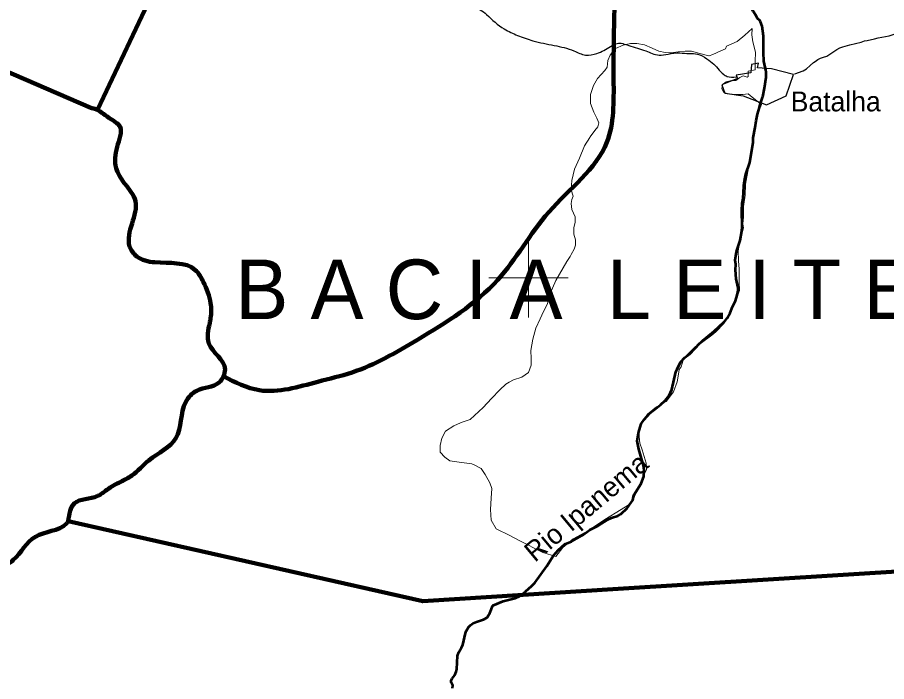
# Model space of a CAD drawing. Extents: x 553962 to 842807, y 8883888 to 9032388.
# Drawn here: x 687122 to 709028, y 8914832 to 8931558 of the extents above; entities that cross this region are included whole.
import ezdxf
from ezdxf.enums import TextEntityAlignment as Align

# ---------------------------------------------------------------- set-up
doc = ezdxf.new("R2010")
doc.units = 0
doc.header["$LTSCALE"] = 200
for name, color, linetype, lineweight in [('12', 7, 'Continuous', 25), ('2', 7, 'Continuous', 13), ('21', 7, 'Continuous', 25), ('24', 7, 'Continuous', 25), ('52', 7, 'Continuous', 13), ('9', 7, 'Continuous', 90)]:
    doc.layers.add(name, color=color, linetype=linetype, lineweight=lineweight)
for name, color, linetype in [('41', 7, 'Continuous'), ('42', 7, 'Continuous'), ('49', 7, 'Continuous')]:
    doc.layers.add(name, color=color, linetype=linetype)

msp = doc.modelspace()

# ---------------------------------------------------------------- linework, layer by layer
at = {"layer": '12'}
for points in [[(708723.4, 8931020.2), (708811.5, 8931041), (709092.4, 8931097.6), (709408.8, 8931206.7)], [(707006.6, 8930266.8), (707103.7, 8930343), (707184.8, 8930419.8), (707230.2, 8930449.4), (707290.2, 8930499.3), (707360.5, 8930533.4), (707440.2, 8930552.8), (707519.1, 8930582), (707648.7, 8930663), (707774.6, 8930753.3), (707847.3, 8930792.2), (707921.9, 8930818.9), (708100.7, 8930870.7), (708389.3, 8930937.4), (708468.4, 8930964.3), (708541.7, 8930977.4), (708723.4, 8931020.2)], [(706708.4, 8930134.1), (706715.6, 8930134.1), (706921.2, 8930211.8), (707006.6, 8930266.8)]]:
    msp.add_lwpolyline(points, dxfattribs=at)
msp.add_spline([(697097.5, 8934365.4), (697137.8, 8934298.3), (697070.7, 8934204.4), (696976.8, 8934097.1), (696963.4, 8933962.9), (696950, 8933681.2), (696923.2, 8933466.6), (696990.2, 8933278.7), (697097.5, 8933131.2), (697285.2, 8932889.7), (697486.4, 8932795.8), (697768, 8932648.2), (698036.2, 8932460.4), (698210.5, 8932205.5), (698344.6, 8932044.5), (698559.1, 8931829.8), (698787.1, 8931749.3), (698948, 8931628.6), (699390.5, 8931266.4), (699725.7, 8931105.4), (700114.6, 8930971.2), (700651, 8930850.5), (701147.1, 8930716.3), (701442.1, 8930609), (701723.7, 8930649.2), (702072.3, 8930823.6), (702233.2, 8930904.1), (702528.2, 8930850.5), (702957.3, 8930716.3), (703292.6, 8930609), (703520.5, 8930635.8), (703815.5, 8930662.7), (704056.9, 8930649.2), (704258, 8930635.8), (704499.4, 8930515.1), (704673.7, 8930380.9), (704807.8, 8930233.3), (704915.1, 8930126), (705008.9, 8930072.4), (705236.9, 8930058.9)], degree=3, dxfattribs=at)
at = {"layer": '2'}
for p, q in [((700000, 8924000), (700000, 8926000)), ((699000, 8925000), (701000, 8925000))]:
    msp.add_line(p, q, dxfattribs=at)
at = {"layer": '21'}
msp.add_lwpolyline([(706124.6, 8930262.6), (705772.7, 8930291), (705798.2, 8930406.1), (705622.6, 8930367.7), (705604.9, 8930160.7), (705235.9, 8930107), (705266.5, 8930017.5), (704872.7, 8929859.6), (704949.4, 8929648.4), (705414.2, 8929583), (706002.8, 8929352.6), (706496.2, 8929580.5), (706680.1, 8930116.3)], close=True, dxfattribs=at)
at = {"layer": '24', "lineweight": 53}
for points in [[(705923, 8930675.2), (705922.4, 8931088), (705890.3, 8931333.3), (705852.8, 8931442.3), (705831.3, 8931475.9), (705777.1, 8931528.7), (705743, 8931598.9), (705663.1, 8931713.6), (705581.9, 8931877.1), (705542.5, 8932009.4), (705503.3, 8932209.2), (705508.2, 8932351.5), (705569.4, 8932508), (705640.5, 8932849.9), (705671.7, 8933352.4), (705678, 8933377.8)], [(705981.1, 8930233.2), (705937.6, 8930459), (705923, 8930675.2)], [(705906.7, 8929556.8), (705952.7, 8929774.7), (705995, 8930056.4), (705991.2, 8930180.9), (705981.1, 8930233.2)], [(705714.4, 8928785), (705737.3, 8928951.8), (705774, 8929122.5), (705823.8, 8929288.7), (705837.1, 8929367.7), (705902.7, 8929538.2), (705906.7, 8929556.8)], [(705581.6, 8927900.5), (705661.4, 8928419), (705668.1, 8928525.9), (705714.4, 8928785)], [(705429.5, 8927325.7), (705443, 8927442.9), (705477.8, 8927613.5), (705581.6, 8927900.5)], [(703328.7, 8921805.4), (703443, 8921908.1), (703548.7, 8922036.8), (703617.1, 8922184), (703718.8, 8922634.2), (703746.2, 8922702.2), (703835.8, 8922872.4), (703941.7, 8922992.8), (704066.1, 8923087.4), (704318, 8923358.7), (704612.5, 8923568.7), (704719.2, 8923658.3), (704922.8, 8923872.7), (705008.7, 8923982.7), (705085.3, 8924116.9), (705144.1, 8924270.4), (705217.1, 8924423.9), (705261.2, 8924562.9), (705283, 8924679.2), (705282.9, 8924744.8), (705239.7, 8924977.1), (705221.2, 8925199.9), (705230.3, 8925333.3), (705211.7, 8925444.3), (705241.2, 8925661.6), (705335.2, 8925935.9), (705376.3, 8926171.8), (705383.6, 8926283.7), (705379.5, 8926700.1), (705390.8, 8926871), (705410.9, 8927000.7), (705427.2, 8927305.4), (705429.5, 8927325.7)], [(700933.1, 8918304.1), (701087.7, 8918357.1), (701353.2, 8918514.3), (701545, 8918649.8), (701747.7, 8918756.1), (702001.1, 8918916), (702097.1, 8918956.4), (702250.9, 8919005.3), (702331, 8919046.8), (702493.5, 8919198.3), (702630.7, 8919399.1), (702659.6, 8919524.5), (702838.4, 8919824.3), (702905.9, 8919998.5), (702914.2, 8920160.2), (702900, 8920271.5), (702779.5, 8920686.8), (702738.4, 8920898.1), (702772.1, 8921093.7), (702813.3, 8921239.1), (702844.7, 8921319.1), (702917.3, 8921435.8), (703064, 8921594.2), (703249.3, 8921734.1), (703328.7, 8921805.4)], [(699106, 8916749.2), (699107.9, 8916751.8), (699364.4, 8916858.8), (699663.1, 8916929.4), (699774, 8916985.7), (699929.5, 8917100.9), (700086.2, 8917240.2), (700161.8, 8917318.8), (700161.8, 8917318.8), (700462.7, 8917739.7), (700633.3, 8918009.2), (700747.4, 8918139), (700925.2, 8918301.4), (700933.1, 8918304.1)], [(698310.3, 8915692), (698345.2, 8915759.1), (698414.2, 8916049.1), (698434, 8916103.3), (698493.2, 8916205.4), (698541, 8916255.4), (698604.5, 8916300.2), (698689, 8916338.6), (698872.4, 8916392.4), (698958.8, 8916447.6), (698989, 8916484.6), (699031.1, 8916558.4), (699106, 8916749.2)], [(698089.5, 8914668.2), (698093, 8914730.9), (698057.9, 8914805.5), (698057.7, 8914860.2), (698080.5, 8914908.2), (698146.1, 8914998.1), (698179.3, 8915082.2), (698193.2, 8915143.2), (698213.4, 8915483.8), (698249.4, 8915574.9), (698249.4, 8915574.9), (698310.3, 8915692)]]:
    msp.add_lwpolyline(points, dxfattribs=at)
at = {"layer": '24'}
for points in [[(705581.6, 8927900.5), (705661.4, 8928419), (705668.1, 8928525.9), (705714.4, 8928785)], [(705429.5, 8927325.7), (705443, 8927442.9), (705477.8, 8927613.5), (705581.6, 8927900.5)], [(703328.7, 8921805.4), (703443, 8921908.1), (703548.7, 8922036.8), (703617.1, 8922184), (703718.8, 8922634.2), (703746.2, 8922702.2), (703835.8, 8922872.4), (703941.7, 8922992.8), (704066.1, 8923087.4), (704318, 8923358.7), (704612.5, 8923568.7), (704719.2, 8923658.3), (704922.8, 8923872.7), (705008.7, 8923982.7), (705085.3, 8924116.9), (705144.1, 8924270.4), (705217.1, 8924423.9), (705261.2, 8924562.9), (705283, 8924679.2), (705282.9, 8924744.8), (705239.7, 8924977.1), (705221.2, 8925199.9), (705230.3, 8925333.3), (705211.7, 8925444.3), (705241.2, 8925661.6), (705335.2, 8925935.9), (705376.3, 8926171.8), (705383.6, 8926283.7), (705379.5, 8926700.1), (705390.8, 8926871), (705410.9, 8927000.7), (705427.2, 8927305.4), (705429.5, 8927325.7)], [(700933.1, 8918304.1), (701087.7, 8918357.1), (701353.2, 8918514.3), (701545, 8918649.8), (701747.7, 8918756.1), (702001.1, 8918916), (702097.1, 8918956.4), (702250.9, 8919005.3), (702331, 8919046.8), (702493.5, 8919198.3), (702630.7, 8919399.1), (702659.6, 8919524.5), (702838.4, 8919824.3), (702905.9, 8919998.5), (702914.2, 8920160.2), (702900, 8920271.5), (702779.5, 8920686.8), (702738.4, 8920898.1), (702772.1, 8921093.7), (702813.3, 8921239.1), (702844.7, 8921319.1), (702917.3, 8921435.8), (703064, 8921594.2), (703249.3, 8921734.1), (703328.7, 8921805.4)], [(699106, 8916749.2), (699107.9, 8916751.8), (699364.4, 8916858.8), (699663.1, 8916929.4), (699774, 8916985.7), (699929.5, 8917100.9), (700086.2, 8917240.2), (700161.8, 8917318.8), (700161.8, 8917318.8), (700462.7, 8917739.7), (700633.3, 8918009.2), (700747.4, 8918139), (700925.2, 8918301.4), (700933.1, 8918304.1)], [(698310.3, 8915692), (698345.2, 8915759.1), (698414.2, 8916049.1), (698434, 8916103.3), (698493.2, 8916205.4), (698541, 8916255.4), (698604.5, 8916300.2), (698689, 8916338.6), (698872.4, 8916392.4), (698958.8, 8916447.6), (698989, 8916484.6), (699031.1, 8916558.4), (699106, 8916749.2)], [(698089.5, 8914668.2), (698093, 8914730.9), (698057.9, 8914805.5), (698057.7, 8914860.2), (698080.5, 8914908.2), (698146.1, 8914998.1), (698179.3, 8915082.2), (698193.2, 8915143.2), (698213.4, 8915483.8), (698249.4, 8915574.9), (698249.4, 8915574.9), (698310.3, 8915692)]]:
    msp.add_lwpolyline(points, dxfattribs=at)
at = {"layer": '52'}
for points in [[(704553.1, 8930592.5), (704645.5, 8930626.1), (704851.5, 8930715.5), (704967.9, 8930769.2), (704994.7, 8930831.8), (705129, 8930894.4), (705263.3, 8930948), (705451.4, 8931109), (705639.4, 8931278.9), (705635.1, 8931118.9), (705653, 8930940.1), (705724.6, 8930680.7), (705715.7, 8930448.2), (705715.7, 8930233.6), (705536.2, 8930202.8), (705536.2, 8930068.6), (705509.3, 8930050.7), (705410.9, 8930086.5), (705330.3, 8930041.8), (705231.8, 8929970.3), (705115.4, 8929970.3), (704981.1, 8929934.5), (704891.5, 8929871.9), (704873.6, 8929755.6)], [(704553.1, 8930592.5), (704645.5, 8930626.1), (704851.5, 8930715.5), (704967.9, 8930769.2), (704994.7, 8930831.8), (705129, 8930894.4), (705263.3, 8930948), (705451.4, 8931109), (705639.4, 8931278.9), (705635.1, 8931118.9), (705653, 8930940.1), (705724.6, 8930680.7), (705715.7, 8930448.2), (705715.7, 8930233.6), (705536.2, 8930202.8), (705536.2, 8930068.6), (705509.3, 8930050.7), (705410.9, 8930086.5), (705330.3, 8930041.8), (705231.8, 8929970.3), (705115.4, 8929970.3), (704981.1, 8929934.5), (704891.5, 8929871.9), (704873.6, 8929755.6)], [(704873.6, 8929755.6), (704891.5, 8929871.9), (704981.1, 8929934.5), (705115.4, 8929970.3), (705231.8, 8929970.3), (705330.3, 8930041.8), (705410.9, 8930086.5), (705509.3, 8930050.7), (705536.2, 8930068.6), (705536.2, 8930202.8), (705715.7, 8930233.6), (705715.7, 8930448.2), (705724.6, 8930680.7), (705653, 8930940.1), (705635.1, 8931118.9), (705639.4, 8931278.9), (705451.4, 8931109), (705263.3, 8930948), (705129, 8930894.4), (704994.7, 8930831.8), (704967.9, 8930769.2), (704851.5, 8930715.5), (704645.5, 8930626.1), (704553.1, 8930592.5)], [(702167.3, 8930746.7), (702192.2, 8930778.1), (702389.1, 8930858.6), (702577.2, 8930903.3), (702729.4, 8930903.3), (702926.4, 8930867.6), (703123.3, 8930787.1), (703284.5, 8930706.6), (703445.7, 8930670.8), (703553.4, 8930664.5)], [(702167.3, 8930746.7), (702192.2, 8930778.1), (702389.1, 8930858.6), (702577.2, 8930903.3), (702729.4, 8930903.3), (702926.4, 8930867.6), (703123.3, 8930787.1), (703284.5, 8930706.6), (703445.7, 8930670.8), (703553.4, 8930664.5)], [(703553.4, 8930664.5), (703445.7, 8930670.8), (703284.5, 8930706.6), (703123.3, 8930787.1), (702926.4, 8930867.6), (702729.4, 8930903.3), (702577.2, 8930903.3), (702389.1, 8930858.6), (702192.2, 8930778.1), (702167.3, 8930746.7)], [(701561.1, 8928552.9), (701672.8, 8928712.3), (701753.4, 8928801.7), (701771.3, 8928900.1), (701726.6, 8929016.3), (701646, 8929168.4), (701565.4, 8929391.9), (701565.4, 8929615.5), (701637, 8929839.1), (701744.5, 8930018), (701925.4, 8930217.4), (701986.2, 8930304.1), (702004.1, 8930474.1), (702057.8, 8930608.2), (702167.3, 8930746.7)], [(701561.1, 8928552.9), (701672.8, 8928712.3), (701753.4, 8928801.7), (701771.3, 8928900.1), (701726.6, 8929016.3), (701646, 8929168.4), (701565.4, 8929391.9), (701565.4, 8929615.5), (701637, 8929839.1), (701744.5, 8930018), (701925.4, 8930217.4), (701986.2, 8930304.1), (702004.1, 8930474.1), (702057.8, 8930608.2), (702167.3, 8930746.7)], [(702167.3, 8930746.7), (702057.8, 8930608.2), (702004.1, 8930474.1), (701986.2, 8930304.1), (701925.4, 8930217.4), (701744.5, 8930018), (701637, 8929839.1), (701565.4, 8929615.5), (701565.4, 8929391.9), (701646, 8929168.4), (701726.6, 8929016.3), (701771.3, 8928900.1), (701753.4, 8928801.7), (701672.8, 8928712.3), (701561.1, 8928552.9)], [(703553.4, 8930664.5), (703597.9, 8930661.9), (703777, 8930688.7), (703947.1, 8930706.6), (704108.3, 8930706.6), (704323.2, 8930652.9)], [(703553.4, 8930664.5), (703597.9, 8930661.9), (703777, 8930688.7), (703947.1, 8930706.6), (704108.3, 8930706.6), (704323.2, 8930652.9)], [(704323.2, 8930652.9), (704108.3, 8930706.6), (703947.1, 8930706.6), (703777, 8930688.7), (703597.9, 8930661.9), (703553.4, 8930664.5)], [(704323.2, 8930652.9), (704547, 8930590.3), (704553.1, 8930592.5)], [(704323.2, 8930652.9), (704547, 8930590.3), (704553.1, 8930592.5)], [(704553.1, 8930592.5), (704547, 8930590.3), (704323.2, 8930652.9)], [(704873.6, 8929755.6), (704927.3, 8929666.2), (705052.7, 8929630.4), (705222.8, 8929612.5), (705401.9, 8929612.5), (705536.2, 8929630.4), (705637.2, 8929550.8), (705759.7, 8929454.2), (705876.5, 8929362.1), (705795.9, 8929183.3), (705742.2, 8928932.9), (705688.4, 8928646.7), (705643.7, 8928342.6), (705598.9, 8928065.4), (705527, 8927674.5), (705473.2, 8927361.5), (705464.3, 8927084.2), (705419.5, 8926798.1), (705419.5, 8926529.8), (705401.6, 8926359.8), (705419.5, 8926261.5), (705374.7, 8926055.8), (705321, 8925868), (705312.9, 8925825.5)], [(704873.6, 8929755.6), (704927.3, 8929666.2), (705052.7, 8929630.4), (705222.8, 8929612.5), (705401.9, 8929612.5), (705536.2, 8929630.4), (705637.2, 8929550.8), (705759.7, 8929454.2), (705876.5, 8929362.1), (705795.9, 8929183.3), (705742.2, 8928932.9), (705688.4, 8928646.7), (705643.7, 8928342.6), (705598.9, 8928065.4), (705527, 8927674.5), (705473.2, 8927361.5), (705464.3, 8927084.2), (705419.5, 8926798.1), (705419.5, 8926529.8), (705401.6, 8926359.8), (705419.5, 8926261.5), (705374.7, 8926055.8), (705321, 8925868), (705312.9, 8925825.5)], [(705637.2, 8929550.8), (705536.2, 8929630.4), (705401.9, 8929612.5), (705222.8, 8929612.5), (705052.7, 8929630.4), (704927.3, 8929666.2), (704873.6, 8929755.6)], [(705276.5, 8924574.1), (705321, 8924678.6), (705312.1, 8924902.1), (705312.1, 8925215.1), (705294.2, 8925429.8), (705285.2, 8925680.2), (705312.9, 8925825.5), (705321, 8925868), (705374.7, 8926055.8), (705419.5, 8926261.5), (705401.6, 8926359.8), (705419.5, 8926529.8), (705419.5, 8926798.1), (705464.3, 8927084.2), (705473.2, 8927361.5), (705527, 8927674.5), (705598.9, 8928065.4), (705643.7, 8928342.6), (705688.4, 8928646.7), (705742.2, 8928932.9), (705795.9, 8929183.3), (705876.5, 8929362.1), (705759.7, 8929454.2), (705637.2, 8929550.8)], [(701561.1, 8928552.9), (701547.5, 8928533.4), (701413.2, 8928327.7), (701286.5, 8928016.8), (701161.1, 8927739.6), (701098.4, 8927453.4), (701080.5, 8927211.9), (701125.3, 8927059.9), (701098.4, 8926970.5), (701080.5, 8926872.1), (701098.4, 8926720.1), (701179, 8926532.3), (701179, 8926398.1), (701143.2, 8926255), (701143.2, 8926103), (701188, 8925959.9), (701188, 8925825.8), (701152.2, 8925718.4), (701080.5, 8925584.3), (701050.8, 8925537.3), (700973.1, 8925414.4), (700694.8, 8924934.2), (700551.5, 8924603.3), (700479.9, 8924352.9), (700336.6, 8924057.7), (700292.8, 8923965), (700184.4, 8923735.8), (700112.8, 8923458.6), (700059.1, 8923172.4), (700068, 8922966.7), (700067.3, 8922798.3), (700004.7, 8922619.4), (699834.5, 8922494.2), (699628.6, 8922431.6), (699519.3, 8922372.1), (699431.6, 8922324.3), (699279.4, 8922181.2), (699073.4, 8921957.7), (698858.6, 8921734.1), (698639.4, 8921533.7)], [(701050.8, 8925537.3), (701080.5, 8925584.3), (701152.2, 8925718.4), (701188, 8925825.8), (701188, 8925959.9), (701143.2, 8926103), (701143.2, 8926255), (701179, 8926398.1), (701179, 8926532.3), (701098.4, 8926720.1), (701080.5, 8926872.1), (701098.4, 8926970.5), (701125.3, 8927059.9), (701080.5, 8927211.9), (701098.4, 8927453.4), (701161.1, 8927739.6), (701286.5, 8928016.8), (701413.2, 8928327.7), (701547.5, 8928533.4), (701561.1, 8928552.9)], [(701050.8, 8925537.3), (701080.5, 8925584.3), (701152.2, 8925718.4), (701188, 8925825.8), (701188, 8925959.9), (701143.2, 8926103), (701143.2, 8926255), (701179, 8926398.1), (701179, 8926532.3), (701098.4, 8926720.1), (701080.5, 8926872.1), (701098.4, 8926970.5), (701125.3, 8927059.9), (701080.5, 8927211.9), (701098.4, 8927453.4), (701161.1, 8927739.6), (701286.5, 8928016.8), (701413.2, 8928327.7), (701547.5, 8928533.4), (701561.1, 8928552.9)], [(705312.9, 8925825.5), (705285.2, 8925680.2), (705294.2, 8925429.8), (705312.1, 8925215.1), (705312.1, 8924902.1), (705321, 8924678.6), (705276.5, 8924574.1), (705276.5, 8924574.1), (705229.7, 8924464.4), (705068.5, 8924061.9), (704907.3, 8923892), (704665.6, 8923668.4), (704379, 8923427), (704065.7, 8923131.9), (703931.3, 8922997.7), (703904.5, 8922926.2), (703850.8, 8922756.3), (703797, 8922693.7), (703779.1, 8922577.4), (703752.3, 8922380.7), (703653.8, 8922130.2), (703474.7, 8921888.8), (703231.4, 8921748.3), (702998.6, 8921569.4), (702882.2, 8921399.5), (702801.7, 8921211.7), (702792.7, 8920997.1), (702810.6, 8920836.1), (702864.3, 8920666.2), (702971.8, 8920335.3), (702980.7, 8920174.3), (702918.1, 8920049.1), (702783.7, 8919745), (702649.4, 8919432), (702515.1, 8919271.1), (702339.9, 8919165.6), (701928, 8918915.2), (701498.2, 8918629), (701131.1, 8918423.3), (700871.4, 8918208.7)], [(705312.9, 8925825.5), (705285.2, 8925680.2), (705294.2, 8925429.8), (705312.1, 8925215.1), (705312.1, 8924902.1), (705321, 8924678.6), (705276.5, 8924574.1), (705276.5, 8924574.1), (705229.7, 8924464.4), (705068.5, 8924061.9), (704907.3, 8923892), (704665.6, 8923668.4), (704379, 8923427), (704065.7, 8923131.9), (703931.3, 8922997.7), (703904.5, 8922926.2), (703850.8, 8922756.3), (703797, 8922693.7), (703779.1, 8922577.4), (703752.3, 8922380.7), (703653.8, 8922130.2), (703474.7, 8921888.8), (703231.4, 8921748.3), (702998.6, 8921569.4), (702882.2, 8921399.5), (702801.7, 8921211.7), (702792.7, 8920997.1), (702810.6, 8920836.1), (702864.3, 8920666.2), (702971.8, 8920335.3), (702980.7, 8920174.3), (702918.1, 8920049.1), (702783.7, 8919745), (702649.4, 8919432), (702515.1, 8919271.1), (702339.9, 8919165.6), (701928, 8918915.2), (701498.2, 8918629), (701131.1, 8918423.3), (700871.4, 8918208.7)], [(700112.8, 8923458.6), (700184.4, 8923735.8), (700292.8, 8923965), (700336.6, 8924057.7), (700479.9, 8924352.9), (700551.5, 8924603.3), (700694.8, 8924934.2), (700973.1, 8925414.4), (701050.8, 8925537.3)], [(700112.8, 8923458.6), (700184.4, 8923735.8), (700292.8, 8923965), (700336.6, 8924057.7), (700479.9, 8924352.9), (700551.5, 8924603.3), (700694.8, 8924934.2), (700973.1, 8925414.4), (701050.8, 8925537.3)], [(702810.6, 8920836.1), (702792.7, 8920997.1), (702801.7, 8921211.7), (702882.2, 8921399.5), (702998.6, 8921569.4), (703231.4, 8921748.3), (703474.7, 8921888.8), (703653.8, 8922130.2), (703752.3, 8922380.7), (703779.1, 8922577.4), (703797, 8922693.7), (703850.8, 8922756.3), (703904.5, 8922926.2), (703931.3, 8922997.7), (704065.7, 8923131.9), (704379, 8923427), (704665.6, 8923668.4), (704907.3, 8923892), (705068.5, 8924061.9), (705229.7, 8924464.4), (705276.5, 8924574.1), (705276.5, 8924574.1)], [(700871.4, 8918208.7), (700692.3, 8917985.1), (700361.1, 8918083.5), (699769.2, 8918382), (699528.3, 8918512.7), (699185.6, 8918680.8), (699060.2, 8918895.5), (699042.3, 8919163.8), (699060.2, 8919449.9), (699078.2, 8919691.4), (699024.4, 8919834.5), (698908, 8920049.1), (698809.5, 8920201.2), (698633, 8920289.3), (698576.7, 8920317.4), (698254.4, 8920362.1), (698021.6, 8920388.9), (697896.2, 8920487.3), (697779.8, 8920612.5), (697779.8, 8920773.5), (697815.7, 8920961.3), (697914.2, 8921140.2), (698120.1, 8921274.3), (698217.8, 8921315), (698217.8, 8921315), (698335, 8921363.7), (698532, 8921435.3), (698639.4, 8921533.7), (698858.6, 8921734.1), (699073.4, 8921957.7), (699279.4, 8922181.2), (699431.6, 8922324.3), (699519.3, 8922372.1), (699628.6, 8922431.6), (699834.5, 8922494.2), (700004.7, 8922619.4), (700067.3, 8922798.3), (700068, 8922966.7), (700059.1, 8923172.4), (700112.8, 8923458.6)], [(700871.4, 8918208.7), (700692.3, 8917985.1), (700361.1, 8918083.5), (699769.2, 8918382), (699528.3, 8918512.7), (699185.6, 8918680.8), (699060.2, 8918895.5), (699042.3, 8919163.8), (699060.2, 8919449.9), (699078.2, 8919691.4), (699024.4, 8919834.5), (698908, 8920049.1), (698809.5, 8920201.2), (698633, 8920289.3), (698576.7, 8920317.4), (698254.4, 8920362.1), (698021.6, 8920388.9), (697896.2, 8920487.3), (697779.8, 8920612.5), (697779.8, 8920773.5), (697815.7, 8920961.3), (697914.2, 8921140.2), (698120.1, 8921274.3), (698217.8, 8921315), (698217.8, 8921315), (698335, 8921363.7), (698532, 8921435.3), (698639.4, 8921533.7), (698858.6, 8921734.1), (699073.4, 8921957.7), (699279.4, 8922181.2), (699431.6, 8922324.3), (699519.3, 8922372.1), (699628.6, 8922431.6), (699834.5, 8922494.2), (700004.7, 8922619.4), (700067.3, 8922798.3), (700068, 8922966.7), (700059.1, 8923172.4), (700112.8, 8923458.6)], [(698639.4, 8921533.7), (698532, 8921435.3), (698335, 8921363.7), (698217.8, 8921315), (698217.8, 8921315), (698120.1, 8921274.3), (697914.2, 8921140.2), (697815.7, 8920961.3), (697779.8, 8920773.5), (697779.8, 8920612.5), (697896.2, 8920487.3), (698021.6, 8920388.9), (698254.4, 8920362.1), (698576.7, 8920317.4), (698633, 8920289.3), (698809.5, 8920201.2), (698908, 8920049.1), (699024.4, 8919834.5), (699078.2, 8919691.4), (699060.2, 8919449.9), (699042.3, 8919163.8), (699060.2, 8918895.5), (699185.6, 8918680.8), (699528.3, 8918512.7), (699769.2, 8918382), (700361.1, 8918083.5), (700692.3, 8917985.1), (700871.4, 8918208.7), (701131.1, 8918423.3), (701498.2, 8918629), (701928, 8918915.2), (702339.9, 8919165.6), (702515.1, 8919271.1), (702649.4, 8919432), (702783.7, 8919745), (702918.1, 8920049.1), (702980.7, 8920174.3), (702971.8, 8920335.3), (702864.3, 8920666.2), (702810.6, 8920836.1)]]:
    msp.add_lwpolyline(points, dxfattribs=at)
at = {"layer": '9'}
msp.add_line((702263.2, 8917164.2), (717332.2, 8918103.3), dxfattribs=at)
for points in [[(689144, 8929228.6), (690630.4, 8932380.6), (694006.3, 8932836.1), (696166.5, 8937713.9), (696283.3, 8937647.1)], [(688969.4, 8929279), (683955, 8931444.8), (681670, 8933656.4)], [(688404.9, 8918868.1), (697336.5, 8916857.2), (702263.2, 8917164.2)]]:
    msp.add_lwpolyline(points, dxfattribs=at)
for points in [[(702208.9, 8933124.7), (702148.3, 8929984.4), (701978.2, 8928413.1), (700513.8, 8926655.1), (699226.8, 8924948.9), (697202.3, 8923439.9), (695555.4, 8922617.4), (694693, 8922383.1), (693220.9, 8922169.7), (692314.9, 8922520)], [(688404.9, 8918868.1), (688561.4, 8919324.4), (689144.7, 8919506), (689372.6, 8919659.6), (689727.1, 8919864.8), (690005.8, 8920018.8), (690435.7, 8920401.8), (691118.7, 8920963.9), (691368.2, 8921877.4), (691646.2, 8922158), (692203.9, 8922364.7), (692354.7, 8922695), (691945.1, 8923350.3), (691968, 8923856.9), (691992.7, 8923983.7), (691990.8, 8924363.6), (691810.4, 8924894), (691605.7, 8925196.3), (690588.8, 8925391.4), (690130.9, 8925539.9), (689951.8, 8925791.8), (690098.6, 8926932.4), (689816.9, 8927386.1), (689611.9, 8927764.4), (689634.6, 8928296.3), (689708.3, 8928803.3), (689427.8, 8929029.1), (689071.1, 8929254.4), (688969.4, 8929279)], [(685563.3, 8914000.1), (685411.9, 8914186), (685156.8, 8914412), (685077.7, 8914993.8), (685249.9, 8916134.6), (685677.5, 8916973.4), (686082.1, 8917330.9), (686664.7, 8917664.4), (687019.1, 8917894.9), (687575, 8918481.4), (688360.8, 8918816.4), (688404.9, 8918868.1)]]:
    msp.add_spline(points, degree=3, dxfattribs=at)

# ---------------------------------------------------------------- texts
at = {"layer": '41'}
msp.add_text('Batalha', height=500, dxfattribs=at).set_placement((706611.1, 8929191.2))
at = {"layer": '42'}
msp.add_text('B A C I A  L E I T E I R A', height=1500, dxfattribs=at).set_placement((703704.8, 8923960), align=Align.CENTER)
at = {"layer": '49'}
msp.add_text('Rio Ipanema', height=500, rotation=39.92, dxfattribs=at).set_placement((701615.3, 8919036.7), align=Align.CENTER)

doc.saveas('drawing.dxf')
